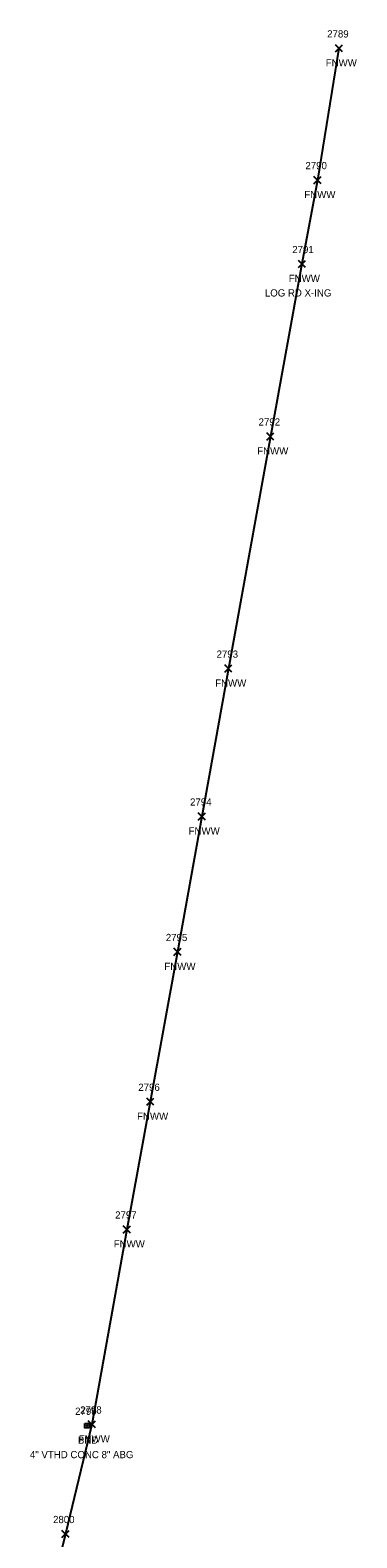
# Model space of a CAD drawing. Extents: x 1472022 to 1479249, y 777216 to 786527.
# Drawn here: x 1473297.8 to 1473388.2, y 779074.7 to 779492 of the extents above; entities that cross this region are included whole.
import ezdxf

# ---------------------------------------------------------------- set-up
doc = ezdxf.new("R2010")
doc.units = 0
for name, color, linetype in [('L_A', 7, 'Continuous'), ('L_C', 7, 'Continuous'), ('L_I', 7, 'Continuous'), ('L_TIC', 7, 'Continuous'), ('Level 18', 7, 'Continuous'), ('LFNC', 7, 'Continuous'), ('M_A', 7, 'Continuous'), ('M_C', 7, 'Continuous'), ('M_I', 7, 'Continuous')]:
    doc.layers.add(name, color=color, linetype=linetype)

msp = doc.modelspace()

# ---------------------------------------------------------------- linework, layer by layer
at = {"layer": 'L_TIC'}
for points in [[(1473382.24, 779485.96), (1473384.24, 779487.96)], [(1473384.24, 779485.96), (1473382.24, 779487.96)], [(1473376.3, 779449.5), (1473378.3, 779451.5)], [(1473378.3, 779449.5), (1473376.3, 779451.5)], [(1473372, 779426.27), (1473374, 779428.27)], [(1473374, 779426.27), (1473372, 779428.27)], [(1473363.25, 779378.55), (1473365.25, 779380.55)], [(1473365.25, 779378.55), (1473363.25, 779380.55)], [(1473351.62, 779314.29), (1473353.62, 779316.29)], [(1473353.62, 779314.29), (1473351.62, 779316.29)], [(1473344.28, 779273.36), (1473346.28, 779275.36)], [(1473346.28, 779273.36), (1473344.28, 779275.36)], [(1473337.57, 779235.86), (1473339.57, 779237.86)], [(1473339.57, 779235.86), (1473337.57, 779237.86)], [(1473330.01, 779194.41), (1473332.01, 779196.41)], [(1473332.01, 779194.41), (1473330.01, 779196.41)], [(1473323.54, 779159.06), (1473325.54, 779161.06)], [(1473325.54, 779159.06), (1473323.54, 779161.06)], [(1473313.86, 779105.1), (1473315.86, 779107.1)], [(1473315.86, 779105.1), (1473313.86, 779107.1)], [(1473306.53, 779074.77), (1473308.53, 779076.77)], [(1473308.53, 779074.77), (1473306.53, 779076.77)]]:
    msp.add_lwpolyline(points, dxfattribs=at)
at = {"layer": 'Level 18'}
msp.add_lwpolyline([(1473312.86, 779106.36), (1473314.11, 779106.36), (1473314.11, 779105.11), (1473312.86, 779105.11)], close=True, dxfattribs=at)
msp.add_circle((1473313.48, 779105.74), 0.0833, dxfattribs=at)
at = {"layer": 'LFNC'}
msp.add_lwpolyline([(1473383.24, 779486.96), (1473377.3, 779450.5), (1473373, 779427.27), (1473364.25, 779379.55), (1473352.62, 779315.29), (1473345.28, 779274.36), (1473338.57, 779236.86), (1473331.01, 779195.41), (1473324.54, 779160.06), (1473314.86, 779106.1), (1473307.53, 779075.77), (1473302.37, 779055.02)], dxfattribs=at)

# ---------------------------------------------------------------- texts
at = {"layer": 'L_A'}
for p in [(1473379.58, 779481.96), (1473373.65, 779445.5), (1473369.35, 779422.27), (1473360.6, 779374.55), (1473348.97, 779310.29), (1473341.63, 779269.36), (1473334.91, 779231.86), (1473327.35, 779190.41), (1473320.89, 779155.06), (1473311.2, 779101.1)]:
    msp.add_text('FNWW', height=2, dxfattribs=at).set_placement(p)
at = {"layer": 'L_C'}
msp.add_text('LOG RD X-ING', height=2, dxfattribs=at).set_placement((1473362.72, 779418.27))
at = {"layer": 'L_I'}
for s, p in [('2789', (1473379.97, 779489.96)), ('2790', (1473373.95, 779453.5)), ('2791', (1473370.31, 779430.27)), ('2792', (1473360.99, 779382.55)), ('2793', (1473349.36, 779318.29)), ('2794', (1473342.02, 779277.36)), ('2795', (1473335.31, 779239.86)), ('2796', (1473327.69, 779198.41)), ('2797', (1473321.28, 779163.06)), ('2798', (1473311.6, 779109.1)), ('2800', (1473304.1, 779078.77))]:
    msp.add_text(s, height=2, dxfattribs=at).set_placement(p)
at = {"layer": 'M_A'}
msp.add_text('BND', height=2, dxfattribs=at).set_placement((1473310.97, 779100.74))
at = {"layer": 'M_C'}
msp.add_text('4" VTHD CONC 8" ABG', height=2, dxfattribs=at).set_placement((1473297.7, 779096.74))
at = {"layer": 'M_I'}
msp.add_text('2799', height=2, dxfattribs=at).set_placement((1473310.21, 779108.74))

doc.saveas('drawing.dxf')
